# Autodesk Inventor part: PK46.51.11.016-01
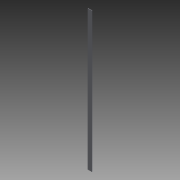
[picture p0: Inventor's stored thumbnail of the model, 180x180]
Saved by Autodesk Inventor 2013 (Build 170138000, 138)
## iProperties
Shininess: 64.0
Length Units: 11269
Angle Units: 11279
Time Units: 11290
Mass Units: 11283
Length Display Precision: 3
Angle Display Precision: 2
Compacted: True
Part Number: PK46.51.11.016-01
Document SubType Name: Листовой материал
Created: 2005-02
Material: Steel, Mild
Designer: =<Author>
Manufacturer: Standard
Standards Organization: Custom
Description: strip
Density: 7.86 g/cm^3
Sheet Metal Rule: По умолчанию
Mass: 88.425 g
Surface Area: 165.45 cm^2
Volume: 11.25 cm^3
Density: 0.0
Volumn: 0.0
Area: 0.0
PropertySet Name: Model Information
Control State: 0
Master: False
Checked Out: False
Checked Out Date: 2008-10-15
Last Check In Date: 2008-10-15
Author: PVitaliy
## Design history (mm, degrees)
node "ФлнОтгиб1"
body "Solid1"
sketch "Эскиз1"
  geometry: L1 (0, 0)-(15, 0)
  constraints: 2 end point, 1 horizontal, 1 other
  dimensions: "d0" = 15 distance of L1.start L1.end
feature "Пластина1" dims "d1" = 500, "d2" = 1.5 (= Ширина_просечки), "d4" = 3 (= Минимальный_остаток), "d6" = 1.5 (= Радиус_гибки), "d7" = 1.5, "Толщина" = 1.5
feature "Изгиб1" dims "d2" = 1.5 (= Ширина_просечки), "d3" = 0.75 (= Глубина_просечки), "d4" = 3 (= Минимальный_остаток), "d5" = 1.5 (= Радиус_гибки), "d6" = 1.5 (= Радиус_гибки), "d7" = 1.5, "Толщина" = 1.5, "Зазор_стыка" = 0.01
other parameters: "Радиус_гибки" = 1.5 (= Толщина), "Ширина_просечки" = 1.5 (= Толщина), "Глубина_просечки" = 0.75 (= 0.5 x Толщина), "Размер_высечки" = 6 (= 4 x Толщина), "Минимальный_остаток" = 3 (= 2 x Толщина), "Радиус_перехода" = 1.5 (= Радиус_гибки), "JacobiRadiusSize" = 1.5 (= Толщина), "GapSize" = 1.5 (= Толщина)
